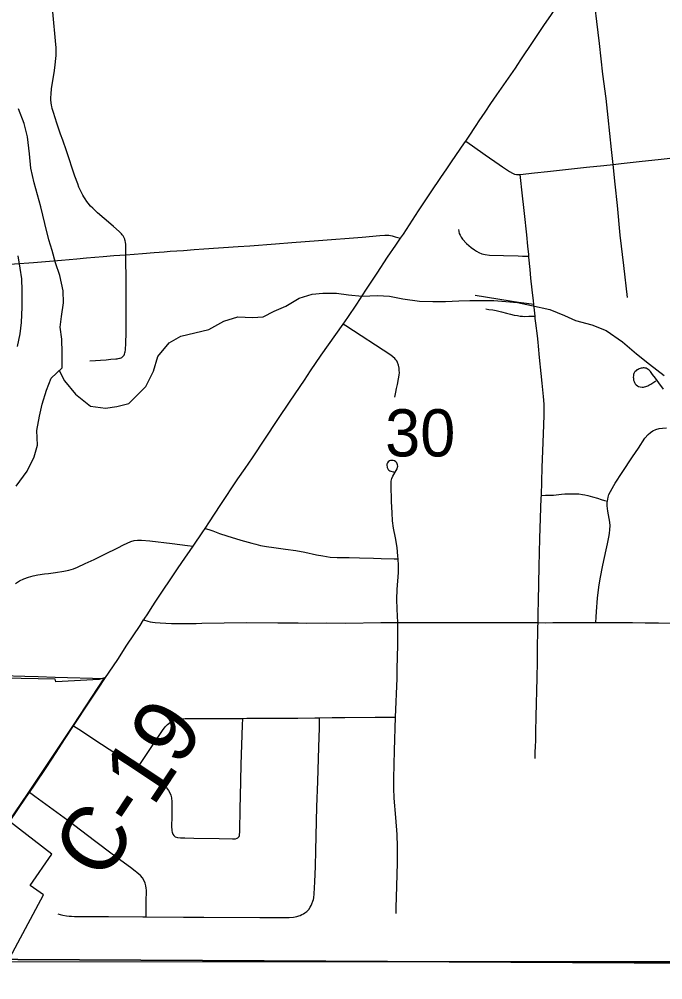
# Model space of a CAD drawing. Extents: x 0 to 34, y 0 to 22.
# Drawn here: x 3.7866 to 4.0719, y 15.2427 to 15.6684 of the extents above; entities that cross this region are included whole.
import ezdxf

# ---------------------------------------------------------------- set-up
doc = ezdxf.new("R2010")
doc.units = 0
for name, color, linetype in [('GM_X_City_Street', 7, 'Continuous'), ('GM_X_Corporation', 7, 'Continuous'), ('GM_X_County_Road', 7, 'Continuous'), ('GM_X_County_Road_Text', 7, 'Continuous'), ('GM_X_Major_River', 7, 'Continuous'), ('GM_X_Minor_River', 7, 'Continuous'), ('GM_X_Section_Text', 7, 'Continuous')]:
    doc.layers.add(name, color=color, linetype=linetype)

msp = doc.modelspace()

# ---------------------------------------------------------------- linework, layer by layer
at = {"layer": 'GM_X_City_Street'}
for points in [[(4.05629, 15.54506), (4.05462, 15.55934), (4.05311, 15.57267), (4.05192, 15.58593), (4.05088, 15.59537), (4.04994, 15.60405), (4.04921, 15.61077), (4.0477, 15.62489), (4.04679, 15.63334), (4.04539, 15.64411), (4.04386, 15.65763), (4.04273, 15.66749), (4.04126, 15.68005), (4.04014, 15.68893), (4.03922, 15.69522)], [(3.83386, 15.56406), (3.83387, 15.56678), (3.83387, 15.56755), (3.83386, 15.56804), (3.83381, 15.56883), (3.83377, 15.56921), (3.83372, 15.56957), (3.8336, 15.57019), (3.83346, 15.57069), (3.83335, 15.57099), (3.83322, 15.57131), (3.83291, 15.57192), (3.83265, 15.57237), (3.83227, 15.57292), (3.83191, 15.57336), (3.83091, 15.5744), (3.82834, 15.5766), (3.82715, 15.57761), (3.82129, 15.5827), (3.81917, 15.5847), (3.81825, 15.58563), (3.81712, 15.58698), (3.81658, 15.58767), (3.8158, 15.58881), (3.81525, 15.58968), (3.81484, 15.59039), (3.8145, 15.591), (3.81391, 15.59218), (3.81309, 15.59403), (3.8125, 15.59547), (3.81124, 15.5989), (3.80749, 15.6101), (3.8059, 15.61476), (3.80496, 15.61755), (3.80332, 15.62233), (3.80172, 15.62713), (3.80121, 15.62881), (3.801, 15.62982), (3.80088, 15.6304), (3.80074, 15.63137), (3.80065, 15.63273), (3.80064, 15.63376), (3.80069, 15.63517), (3.80093, 15.6378), (3.80201, 15.64474), (3.80252, 15.64812), (3.80271, 15.64974), (3.80293, 15.65239), (3.80298, 15.65477), (3.80294, 15.65596), (3.80285, 15.65728), (3.80148, 15.67168)], [(3.98456, 15.61439), (3.98759, 15.61226), (3.9932, 15.60832), (3.99935, 15.60405), (4.00088, 15.60302), (4.00399, 15.60102), (4.00532, 15.6002), (4.00622, 15.59982), (4.00712, 15.59962), (4.00798, 15.59961), (4.00865, 15.59967)], [(4.04994, 15.60405), (4.05349, 15.60442), (4.06274, 15.60547), (4.06984, 15.6063), (4.07912, 15.60726), (4.085, 15.60812), (4.08872, 15.60878), (4.0917, 15.60942)], [(4.00865, 15.59967), (4.01252, 15.60003), (4.01378, 15.60017), (4.01498, 15.6003), (4.02082, 15.60102), (4.03811, 15.60286), (4.04578, 15.60361), (4.04994, 15.60405)], [(4.0153, 15.34087), (4.01533, 15.34208), (4.01542, 15.34392), (4.01551, 15.34576), (4.01554, 15.34668), (4.01561, 15.34822), (4.01571, 15.35257), (4.01585, 15.3594), (4.01621, 15.3765), (4.01635, 15.38364), (4.01639, 15.38768), (4.0164, 15.39047), (4.01652, 15.39699), (4.01658, 15.39884), (4.01662, 15.40101), (4.01668, 15.40503), (4.01681, 15.41075), (4.01715, 15.42595), (4.01748, 15.43835), (4.01808, 15.45637), (4.01811, 15.45739), (4.01845, 15.46973), (4.01888, 15.4809), (4.01916, 15.48862), (4.01932, 15.4929), (4.0193, 15.49786), (4.0191, 15.50126), (4.0185, 15.50713), (4.01798, 15.51145), (4.01728, 15.51856), (4.01684, 15.52352), (4.01665, 15.52537), (4.01637, 15.52815), (4.01568, 15.53368), (4.01542, 15.53583), (4.01532, 15.53689), (4.0148, 15.54218), (4.01467, 15.54356), (4.01407, 15.5485), (4.01347, 15.55374), (4.0131, 15.55745), (4.01259, 15.56298), (4.01255, 15.56344), (4.01247, 15.56421), (4.01208, 15.56791), (4.0116, 15.57284), (4.01065, 15.5824), (4.00951, 15.59289), (4.009, 15.5969), (4.00865, 15.59967)], [(3.83386, 15.56406), (3.84119, 15.56459), (3.84644, 15.56508), (3.85078, 15.56538), (3.85357, 15.5656), (3.85946, 15.566), (3.8641, 15.56633), (3.86843, 15.56663), (3.88362, 15.56764), (3.8889, 15.56797), (3.90024, 15.56891), (3.9075, 15.56951), (3.91931, 15.57038), (3.93859, 15.57182), (3.94645, 15.57263), (3.94866, 15.57279), (3.94963, 15.5728), (3.95049, 15.57272), (3.95117, 15.57261), (3.95197, 15.57242), (3.95323, 15.57206), (3.95569, 15.57134)], [(3.98138, 15.57525), (3.98152, 15.57429), (3.98171, 15.57349), (3.98205, 15.57268), (3.98247, 15.57187), (3.98314, 15.57098), (3.98485, 15.56911), (3.98693, 15.56728), (3.98843, 15.56617), (3.98928, 15.56563), (3.99031, 15.56507), (3.99175, 15.56447), (3.99325, 15.5641), (3.99511, 15.5639), (4.00128, 15.56368), (4.00775, 15.56353), (4.0098, 15.56349), (4.01255, 15.56344)], [(3.76346, 15.55832), (3.76408, 15.55837), (3.76996, 15.55888), (3.78451, 15.56005), (3.79288, 15.56067), (3.80528, 15.56164), (3.81208, 15.56223), (3.8164, 15.56269), (3.82376, 15.56332), (3.82849, 15.56367), (3.83386, 15.56406)], [(3.8179, 15.51697), (3.82034, 15.51717), (3.82261, 15.51734), (3.82514, 15.51753), (3.82721, 15.51771), (3.82947, 15.51794), (3.83007, 15.518), (3.83048, 15.51806), (3.83101, 15.51816), (3.83134, 15.51825), (3.83176, 15.51839), (3.83205, 15.51853), (3.83259, 15.51891), (3.83288, 15.51922), (3.83312, 15.51961), (3.83329, 15.52001), (3.83346, 15.52062), (3.83354, 15.52103), (3.83366, 15.52192), (3.83376, 15.52271), (3.83386, 15.52417), (3.8339, 15.52528), (3.834, 15.52903), (3.834, 15.53504), (3.83397, 15.53976), (3.83404, 15.55114), (3.83386, 15.56406)], [(3.98874, 15.54616), (4.00433, 15.5437), (4.00799, 15.54309), (4.01026, 15.54278), (4.01152, 15.54261), (4.0148, 15.54218)], [(3.99353, 15.54005), (3.99476, 15.53986), (3.9966, 15.53959), (3.99806, 15.53929), (4.0004, 15.53875), (4.0027, 15.5381), (4.00443, 15.53768), (4.00604, 15.53733), (4.00753, 15.53706), (4.00868, 15.53691), (4.00972, 15.5368), (4.01064, 15.53676), (4.01248, 15.5368), (4.01532, 15.53689)], [(3.95311, 15.50098), (3.95362, 15.50315), (3.95393, 15.50481), (3.95433, 15.50659), (3.9548, 15.50904), (3.955, 15.51067), (3.95516, 15.51185), (3.95512, 15.5128), (3.95505, 15.51374), (3.95476, 15.51506), (3.95432, 15.51633), (3.95401, 15.51699), (3.95361, 15.51755), (3.9531, 15.51814), (3.95231, 15.51881), (3.95128, 15.51949), (3.93142, 15.53249), (3.93026, 15.53325)], [(4.07221, 15.5045), (4.0702, 15.50726), (4.06864, 15.50935), (4.06744, 15.51101), (4.0665, 15.51225), (4.06587, 15.51294), (4.06545, 15.51326), (4.06503, 15.51352), (4.06456, 15.51373), (4.06413, 15.51383), (4.06365, 15.51388), (4.06317, 15.51391), (4.06273, 15.51386), (4.06231, 15.51378), (4.06185, 15.51365), (4.06143, 15.5135), (4.06097, 15.51326), (4.0605, 15.513), (4.06006, 15.51267), (4.05975, 15.51233), (4.05944, 15.51196), (4.05913, 15.51142), (4.05897, 15.51101), (4.05889, 15.51044), (4.05884, 15.50981), (4.05889, 15.5093), (4.05902, 15.50852), (4.05923, 15.50782), (4.05941, 15.50738), (4.0597, 15.50689), (4.06014, 15.50639), (4.06066, 15.50601), (4.06123, 15.50569), (4.06195, 15.50549), (4.06286, 15.50536), (4.06338, 15.50538), (4.06384, 15.50546), (4.06436, 15.5056), (4.06483, 15.50575), (4.06532, 15.50597), (4.06581, 15.50621), (4.06669, 15.50676), (4.06757, 15.50733), (4.06884, 15.50818)], [(4.04218, 15.40112), (4.04237, 15.40347), (4.04258, 15.40595), (4.04304, 15.41182), (4.04357, 15.41673), (4.04415, 15.42039), (4.04539, 15.42645), (4.04683, 15.43325), (4.04737, 15.43592), (4.04799, 15.43894), (4.04824, 15.44048), (4.04847, 15.44234), (4.04853, 15.44385), (4.04841, 15.44561), (4.04758, 15.45043), (4.04742, 15.45161), (4.0473, 15.45282), (4.04731, 15.45431), (4.04738, 15.45484), (4.0475, 15.45579), (4.0477, 15.45666), (4.04808, 15.45778), (4.0487, 15.45915), (4.04942, 15.46049), (4.05022, 15.46179), (4.05087, 15.46283), (4.05391, 15.46751), (4.05853, 15.4745), (4.0611, 15.47837), (4.06403, 15.48274), (4.06539, 15.48435), (4.06651, 15.48531), (4.0675, 15.48596), (4.06884, 15.48657), (4.07027, 15.48699), (4.07175, 15.48723), (4.07356, 15.48739)], [(3.95443, 15.4011), (3.95409, 15.40696), (3.95407, 15.41141), (3.95417, 15.41576), (3.95472, 15.42319), (3.9548, 15.42629), (3.95461, 15.42926), (3.95453, 15.43055), (3.95417, 15.43427), (3.9534, 15.43859), (3.9526, 15.44282), (3.95215, 15.44615), (3.95189, 15.44968), (3.95163, 15.45464), (3.95148, 15.4621), (3.95154, 15.46365), (3.95176, 15.46486), (3.95224, 15.466), (3.95372, 15.46838), (3.9541, 15.46922), (3.95431, 15.46994), (3.95439, 15.4703), (3.95435, 15.47094), (3.95423, 15.47138), (3.95395, 15.47186), (3.9535, 15.47228), (3.95295, 15.4727), (3.95235, 15.4729), (3.95179, 15.47294), (3.95127, 15.47286), (3.95075, 15.47266), (3.95023, 15.4723), (3.94987, 15.4719), (3.94963, 15.4713), (3.94959, 15.47062), (3.94967, 15.47014), (3.94977, 15.4698), (3.94987, 15.4695), (3.95002, 15.4692), (3.95019, 15.46893), (3.95051, 15.46861), (3.95091, 15.46834), (3.95139, 15.46813), (3.95196, 15.46797), (3.95255, 15.46781), (3.95288, 15.46773)], [(4.01811, 15.45739), (4.01994, 15.45745), (4.02352, 15.45757), (4.02698, 15.45793), (4.02847, 15.45805), (4.0302, 15.45814), (4.03257, 15.45814), (4.03471, 15.45805), (4.03636, 15.45786), (4.03744, 15.45765), (4.03869, 15.45737), (4.04074, 15.45677), (4.04299, 15.45612), (4.04461, 15.45564), (4.04613, 15.4552), (4.04738, 15.45484)], [(3.86898, 15.4428), (3.87068, 15.44225), (3.87247, 15.44168), (3.87538, 15.44056), (3.87864, 15.43949), (3.88489, 15.43756), (3.88969, 15.4362), (3.89157, 15.43574), (3.89363, 15.43526), (3.89625, 15.43473), (3.89942, 15.43428), (3.9046, 15.43365), (3.90922, 15.43302), (3.91328, 15.4322), (3.91842, 15.43108), (3.92125, 15.43056), (3.92442, 15.43008), (3.92754, 15.4299), (3.93285, 15.42982), (3.93752, 15.42979), (3.94371, 15.42958), (3.94708, 15.42942), (3.95289, 15.4293), (3.95461, 15.42926)], [(3.78491, 15.41842), (3.78672, 15.41955), (3.78862, 15.42048), (3.79064, 15.42119), (3.7927, 15.42175), (3.79479, 15.42217), (3.7978, 15.42259), (3.79962, 15.42282), (3.80269, 15.42323), (3.80639, 15.4238), (3.80853, 15.4243), (3.81065, 15.42491), (3.81243, 15.42557), (3.81582, 15.42717), (3.81978, 15.42901), (3.8245, 15.43139), (3.83033, 15.4342), (3.83276, 15.43547), (3.83609, 15.43693), (3.83753, 15.43735), (3.83901, 15.43754), (3.84082, 15.43757), (3.8445, 15.4372), (3.85439, 15.43603), (3.8612, 15.43526), (3.86377, 15.43497)], [(3.84176, 15.4022), (3.84358, 15.4017), (3.84467, 15.40145), (3.8457, 15.40127), (3.84693, 15.40107), (3.84913, 15.40086), (3.85412, 15.40065), (3.85848, 15.40061), (3.865, 15.40069), (3.86748, 15.40077), (3.87742, 15.40096), (3.88736, 15.40109), (3.90132, 15.40097), (3.90379, 15.40092), (3.9103, 15.40086), (3.91402, 15.40082), (3.92271, 15.40089), (3.93141, 15.40085), (3.94695, 15.40103), (3.95443, 15.4011), (3.95565, 15.40107), (3.96341, 15.40107), (3.96929, 15.40104), (3.97579, 15.40106), (3.97982, 15.40102), (3.991, 15.40108), (3.99596, 15.4011), (3.99936, 15.40111), (4.00401, 15.40107), (4.00617, 15.40103), (4.01052, 15.40103), (4.01662, 15.40101), (4.01984, 15.401), (4.02325, 15.40103), (4.03192, 15.40109), (4.03533, 15.40111), (4.03999, 15.40111), (4.04218, 15.40112), (4.0437, 15.40113), (4.05051, 15.40113), (4.05854, 15.40105), (4.06412, 15.40097), (4.07001, 15.40095), (4.08026, 15.40078)], [(3.95367, 15.27219), (3.95372, 15.27466), (3.95394, 15.28427), (3.95434, 15.29451), (3.95432, 15.30162), (3.95409, 15.30719), (3.95352, 15.31461), (3.95287, 15.32329), (3.95269, 15.32765), (3.95271, 15.33201), (3.95301, 15.34436), (3.95344, 15.35907), (3.9541, 15.37621), (3.95419, 15.38055), (3.95442, 15.39106), (3.95451, 15.39478), (3.95443, 15.4011)], [(3.77884, 15.37752), (3.78907, 15.37733), (3.79497, 15.37717), (3.80251, 15.3768), (3.82451, 15.37629)], [(3.83902, 15.33665), (3.84062, 15.33905), (3.8468, 15.34834), (3.85007, 15.35329), (3.85124, 15.35479), (3.85235, 15.35595), (3.85364, 15.35694), (3.8548, 15.35755), (3.85634, 15.35809), (3.85793, 15.35837), (3.86015, 15.35849), (3.87383, 15.3585), (3.88568, 15.35861), (3.88749, 15.35863), (3.89806, 15.35865), (3.91017, 15.35865), (3.91762, 15.3588), (3.91971, 15.35884), (3.92539, 15.35895), (3.93098, 15.35899), (3.94434, 15.3591), (3.94744, 15.3591), (3.95148, 15.35908), (3.95344, 15.35907)], [(3.80372, 15.27204), (3.8047, 15.27175), (3.80587, 15.27141), (3.80753, 15.27112), (3.8088, 15.27098), (3.80977, 15.27088), (3.81104, 15.27082), (3.81496, 15.27078), (3.82614, 15.2708), (3.84136, 15.27066), (3.84289, 15.27065), (3.85938, 15.27053), (3.86839, 15.27051), (3.89325, 15.27039), (3.90102, 15.27039), (3.9063, 15.27033), (3.90816, 15.27046), (3.90968, 15.27076), (3.91055, 15.27107), (3.91114, 15.27128), (3.91188, 15.27163), (3.91266, 15.27203), (3.91329, 15.27246), (3.91407, 15.27305), (3.91495, 15.27388), (3.91563, 15.27486), (3.91607, 15.27564), (3.91639, 15.27635), (3.9168, 15.27754), (3.91705, 15.27838), (3.91721, 15.27901), (3.91742, 15.28086), (3.91766, 15.28614), (3.91789, 15.29297), (3.91813, 15.30011), (3.9186, 15.31937), (3.91892, 15.33055), (3.9195, 15.34576), (3.91968, 15.35445), (3.91969, 15.3557), (3.91971, 15.35884)], [(3.8107, 15.35533), (3.81295, 15.35384), (3.82306, 15.34716), (3.83321, 15.34051), (3.83902, 15.33665), (3.84721, 15.33123), (3.85051, 15.32894), (3.85188, 15.32777), (3.85284, 15.32666), (3.85342, 15.32566), (3.85383, 15.32458), (3.85409, 15.32343), (3.85425, 15.32161), (3.85429, 15.31541), (3.85413, 15.31041), (3.85419, 15.30934), (3.85427, 15.30879), (3.85438, 15.3081), (3.85464, 15.30731), (3.85507, 15.30663), (3.85569, 15.30614), (3.85674, 15.30574), (3.85809, 15.30564), (3.86007, 15.30558), (3.86404, 15.30548), (3.87523, 15.30532), (3.88112, 15.30516), (3.88247, 15.30524), (3.88318, 15.30547), (3.88352, 15.30567), (3.88381, 15.30594), (3.88406, 15.30628), (3.88422, 15.30665), (3.8843, 15.30701), (3.8844, 15.30832), (3.88459, 15.3189), (3.8847, 15.32387), (3.88505, 15.33818), (3.88559, 15.35558), (3.88568, 15.35861)], [(3.84289, 15.27065), (3.84291, 15.27403), (3.84294, 15.27713), (3.84298, 15.28245), (3.84291, 15.28336), (3.84277, 15.28437), (3.84244, 15.28563), (3.8419, 15.28683), (3.84118, 15.28792), (3.84033, 15.2889), (3.8396, 15.28955), (3.8388, 15.29026), (3.83797, 15.2909), (3.83592, 15.29245), (3.82844, 15.29801), (3.82, 15.30435), (3.8081, 15.31333), (3.79356, 15.32398), (3.79114, 15.32575)]]:
    msp.add_lwpolyline(points, dxfattribs=at)
at = {"layer": 'GM_X_Corporation'}
for points in [[(4.22989, 15.74816), (4.22309, 15.24934), (3.70377, 15.25213), (3.70332, 15.74532)], [(3.70377, 15.25213), (4.22309, 15.24934), (4.21755, 14.74349), (3.70275, 14.74227), (3.70371, 15.24512)]]:
    msp.add_lwpolyline(points, close=True, dxfattribs=at)
msp.add_lwpolyline([(4.08041, 15.25069), (3.97107, 15.25064), (3.93329, 15.25063), (3.78134, 15.2506), (3.79741, 15.28043), (3.79151, 15.28459), (3.8011, 15.29838), (3.78217, 15.31299), (3.79029, 15.32495), (3.81059, 15.35561), (3.8244, 15.37656), (3.82204, 15.3758), (3.80277, 15.3748), (3.80258, 15.37594), (3.76459, 15.37664)], dxfattribs=at)
at = {"layer": 'GM_X_County_Road'}
for points in [[(3.98456, 15.61439), (3.9858, 15.61621), (3.98919, 15.62135), (3.99058, 15.62339), (3.99314, 15.62727), (3.9957, 15.63115), (3.99831, 15.63498), (4.00659, 15.6468), (4.0076, 15.64835), (4.00892, 15.6504), (4.01442, 15.6586), (4.01655, 15.66165), (4.01945, 15.66604), (4.02227, 15.67011), (4.02931, 15.68035), (4.03296, 15.68574), (4.03922, 15.69522)], [(3.95569, 15.57134), (3.95695, 15.57316), (3.95969, 15.57729), (3.96369, 15.58353), (3.96722, 15.58886), (3.96812, 15.59023), (3.96929, 15.59188), (3.9735, 15.59831), (3.97613, 15.60214), (3.97823, 15.60521), (3.98405, 15.61365), (3.98456, 15.61439)], [(3.93026, 15.53325), (3.93228, 15.53623), (3.93626, 15.54214), (3.94034, 15.54837), (3.94525, 15.55592), (3.94986, 15.56294), (3.95359, 15.5683), (3.95569, 15.57134)], [(3.86898, 15.4428), (3.8709, 15.44568), (3.87566, 15.45294), (3.88357, 15.4648), (3.88675, 15.46936), (3.89001, 15.47412), (3.9013, 15.49111), (3.90679, 15.49914), (3.91304, 15.50842), (3.91579, 15.5126), (3.92053, 15.51952), (3.93026, 15.53325)], [(3.86377, 15.43497), (3.86798, 15.44128), (3.86898, 15.4428)], [(3.84176, 15.4022), (3.84201, 15.40259), (3.84355, 15.40489), (3.84557, 15.40796), (3.8472, 15.41047), (3.85678, 15.42486), (3.85871, 15.42763), (3.86377, 15.43497)], [(3.82451, 15.37629), (3.83029, 15.38475), (3.83437, 15.391), (3.84015, 15.39979), (3.84176, 15.4022)], [(3.8107, 15.35533), (3.81795, 15.36628), (3.82168, 15.37201), (3.82451, 15.37629)], [(3.79114, 15.32575), (3.79371, 15.32947), (3.79849, 15.33672), (3.8029, 15.34348), (3.80663, 15.3492), (3.8107, 15.35533)], [(3.78228, 15.31271), (3.78966, 15.32361), (3.79114, 15.32575)]]:
    msp.add_lwpolyline(points, dxfattribs=at)
at = {"layer": 'GM_X_Major_River'}
for points in [[(3.78527, 15.46152), (3.79007, 15.46813), (3.79315, 15.47455), (3.7947, 15.47966), (3.79437, 15.48612), (3.79555, 15.49256), (3.79673, 15.49786), (3.79868, 15.50411), (3.8008, 15.50941), (3.80558, 15.51392), (3.80562, 15.52056), (3.80548, 15.52664), (3.80476, 15.53196), (3.80536, 15.5367), (3.80617, 15.54276), (3.80601, 15.54807), (3.80455, 15.55492), (3.80269, 15.56043), (3.80121, 15.56595), (3.79973, 15.5707), (3.79788, 15.57793), (3.79623, 15.58534), (3.79327, 15.59599), (3.7918, 15.60245), (3.79109, 15.60872), (3.79019, 15.61631), (3.78872, 15.62221), (3.7863, 15.62868)], [(3.78601, 15.5636), (3.78692, 15.55809), (3.78765, 15.55334), (3.7878, 15.54821), (3.78775, 15.54081), (3.78751, 15.53399), (3.7869, 15.52906), (3.78572, 15.52337)]]:
    msp.add_lwpolyline(points, dxfattribs=at)
at = {"layer": 'GM_X_Minor_River'}
msp.add_lwpolyline([(3.80435, 15.51276), (3.80667, 15.50822), (3.81156, 15.50231), (3.81817, 15.49694), (3.8248, 15.49613), (3.82993, 15.49685), (3.83525, 15.49814), (3.8427, 15.50567), (3.84617, 15.51248), (3.84811, 15.51891), (3.85309, 15.52495), (3.85823, 15.52794), (3.86451, 15.52941), (3.87059, 15.53088), (3.87726, 15.53463), (3.88353, 15.53648), (3.88998, 15.53624), (3.89473, 15.53658), (3.89968, 15.53901), (3.90481, 15.54125), (3.91072, 15.54481), (3.91643, 15.54666), (3.92117, 15.547), (3.92724, 15.54696), (3.93255, 15.54635), (3.93862, 15.54573), (3.94545, 15.54606), (3.95076, 15.54564), (3.95664, 15.54446), (3.96403, 15.54345), (3.96991, 15.54341), (3.9756, 15.54336), (3.98148, 15.5437), (3.98642, 15.54385), (3.99704, 15.54377), (4.00235, 15.54335), (4.00747, 15.54293), (4.01372, 15.54155), (4.02187, 15.53979), (4.0283, 15.53708), (4.03322, 15.53495), (4.04041, 15.533), (4.04685, 15.53049), (4.05402, 15.5255), (4.06024, 15.52014), (4.06609, 15.51554), (4.07251, 15.51056)], dxfattribs=at)

# ---------------------------------------------------------------- texts
at = {"layer": 'GM_X_County_Road_Text'}
msp.add_text('C-19', height=0.028409, rotation=56.4039, dxfattribs=at).set_placement((3.82366, 15.28553))
at = {"layer": 'GM_X_Section_Text'}
msp.add_text('30', height=0.020928, rotation=0, dxfattribs=at).set_placement((3.94882, 15.47467))

doc.saveas('drawing.dxf')
